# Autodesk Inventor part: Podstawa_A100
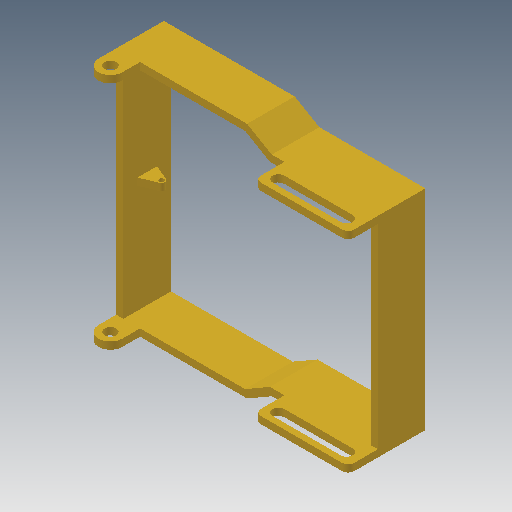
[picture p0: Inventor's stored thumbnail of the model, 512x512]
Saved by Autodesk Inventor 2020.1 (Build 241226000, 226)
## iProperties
Created: 2006-06
Part Number: Podstawa_A100
Document SubType Name: Modeling
Designer: F.Stasiak
Density: 1 g/cm^3
Material: Ogólny
Appearance: Żółty (ciemny)
Manager: www.cadconsulting.pl
Company: Fabian Stasiak CAD Consulting
Author: F.Stasiak
Subject: Zbiór ćwiczeń. Autodesk Inventor 2020. Kurs podstawowy
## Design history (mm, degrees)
sketch "Szkic1"
  geometry: L1 (0, 500)-(550, 500); L2 (1100, 440)-(1100, -440); L3 (550, -500)-(0, -500); L4 (0, -500)-(0, 500); L5 (645.885, 410)-(1070, 410); L6 (1070, 410)-(1070, -410); L7 (1070, -410)-(645.885, -410); L8 (550, 500)-(653.923, 440); L9 (653.923, 440)-(1100, 440); L10 (550, -500)-(653.923, -440); L11 (653.923, -440)-(1100, -440); L12 (30, -470)-(30, 470); L13 (30, 470)-(541.962, 470); L14 (541.962, 470)-(645.885, 410); L15 (30, -470)-(541.962, -470); L16 (541.962, -470)-(645.885, -410); 2 further points
  constraints: 32 end point, 5 parallel, 4 perpendicular, 1 coincident, 1 horizontal, 1 midpoint, 1 other
  dimensions: "d0" = 1000 distance of L3.end L1.start; "d23" = 30 distance between parallel lines of L2 L6; "d24" = 90 distance between parallel lines of L1 L5; "d25" = 90 distance between parallel lines of L3 L7 (= d24); "d26" = 1100 distance between parallel lines of L2 L4; "d27" = 30 distance between parallel lines of L1 L13 (= d23); "d28" = 30 distance between parallel lines of L3 L15 (= d27); "d29" = 30 distance between parallel lines of L4 L12 (= d28); "d30" = 550 distance of L3.start L3.end; "d34" = 30 distance between parallel lines of L7 L11 (= d23); "d35" = 30 distance between parallel lines of L16 L10 (= d36); "d36" = 30 distance between parallel lines of L9 L5 (= d23); "d37" = 150 deg angle of L14 L13; "d38" = 150 deg angle of L16 L15 (= d37)
extrude "Wyciągnięcie proste1" new body sketch "Szkic1" distance "d3" = 200; taper "d4" = 0 deg
sketch "Szkic2"
  geometry: L1 (1100, 200)-(0, 200) reference; L2 (0, 200)-(0, 275); L3 (100, 275)-(100, 200); C1 r 25 at (50, 275); A1 r 50 centre (50, 275) between (100, 275) and (0, 275)
  constraints: 4 end point, 2 centre point, 2 perpendicular, 2 point on circle, 2 tangent, 1 coincident, 1 point on line
  dimensions: "d5" = 50 diameter of C1; "d6" = 50 radius of A1 (= d5); "d7" = 75 distance of L1.end L2.end (= 1.5 x d5)
extrude "Wyciągnięcie proste2" join sketch "Szkic2" distance "d8" = 30; taper "d9" = 0 deg
sketch "Szkic6"
  geometry: L1 (-312.893, -50)-(-25.064, -50); L2 (-25.064, -100)-(-312.893, -100); L3 (-416.077, 0)-(30, 0) reference; L4 (30, 0)-(30, -125); L5 (30, -125)-(-362.893, -125); L6 (-362.893, -125)-(-362.893, 0); C1 r 25 at (-25.064, -75) reference; C2 r 25 at (-312.893, -75) reference; A1 r 25 centre (-25.064, -75) between (-25.064, -100) and (-25.064, -50); A2 r 25 centre (-312.893, -75) between (-312.893, -50) and (-312.893, -100)
  constraints: 10 end point, 4 concentric, 4 point on circle, 3 perpendicular, 3 tangent, 2 centre point, 1 horizontal, 1 point on line
  dimensions: "d39" = 25 distance between parallel lines of L2 L5; "d40" = 50 distance from line of C2.centre L6
extrude "Wyciągnięcie proste6" join sketch "Szkic6" stored distance "d41" = 10; taper "d42" = 0 deg
fillet "Zaokrąglenie2" dims "d43" = 25
mirror "Lustro2"
node "Płaszczyzna konstrukcyjna2"
sketch "Szkic7"
  geometry: L1 (-30, 0)-(-30, 200) reference; L2 (-30, 100)-(-90, 100); L3 (-95.74, 113.858)-(-30, 141.089); L4 (-95.74, 86.142)-(-30, 58.911); L5 (-30, 141.089)-(-30, 58.911); C1 r 10 at (-90, 100); A1 r 15 centre (-90, 100) between (-95.74, 113.858) and (-95.74, 86.142)
  constraints: 8 end point, 2 centre point, 2 coincident, 2 perpendicular, 2 point on circle, 2 point on line, 2 tangent, 1 midpoint, 1 other
  dimensions: "d44" = 30 diameter of A1; "d45" = 20 diameter of C1; "d46" = 60 distance of L2.start L2.end; "d48" = 45 deg angle of L3 L4
extrude "Wyciągnięcie proste7" join sketch "Szkic7" stored distance "d49" = 30; taper "d50" = 0 deg
node "Bryła1"
node "Korpusy bryłowe"
node "Korpusy powierzchniowe"
node "Odniesienie7"
node "Odniesienie8"
